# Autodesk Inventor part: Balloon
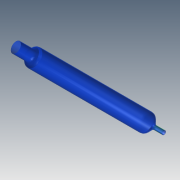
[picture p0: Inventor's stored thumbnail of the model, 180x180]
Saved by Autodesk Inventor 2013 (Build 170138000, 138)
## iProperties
Created: 2013-11
Part Number: Balloon
Material: Generic
Document SubType Name: Modeling
Designer: Warren
Density: 1 g/cm^3
Author: Warren
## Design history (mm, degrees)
sketch "Sketch1"
  geometry: L1 (-2.25, 0.05)-(-1.98, 0.05); L2 (-1.908, 0.08)-(-1.771, 0.22); L3 (-1.7, 0.25)-(1.7, 0.25); L4 (1.771, 0.22)-(1.908, 0.08); L5 (1.98, 0.05)-(2.25, 0.05); L6 (2.25, 0.06)-(1.98, 0.06); L7 (1.915, 0.087)-(1.779, 0.227); L8 (1.7, 0.26)-(-1.7, 0.26); L9 (-1.779, 0.227)-(-1.915, 0.087); L10 (-1.98, 0.06)-(-2.25, 0.06); L11 (2.25, 0.05)-(2.25, 0.06); L12 (-2.25, 0.06)-(-2.25, 0.05); L13 (0, 0)-(1.838, 0); L14 (0, 0)-(0, 0.582); A1 r 0.1 centre (-1.98, 0.15) between (-1.98, 0.05) and (-1.908, 0.08); A2 r 0.1 centre (-1.7, 0.15) between (-1.7, 0.25) and (-1.771, 0.22); A3 r 0.1 centre (1.7, 0.15) between (1.771, 0.22) and (1.7, 0.25); A4 r 0.1 centre (1.98, 0.15) between (1.908, 0.08) and (1.98, 0.05); A5 r 0.09 centre (1.98, 0.15) between (1.915, 0.087) and (1.98, 0.06); A6 r 0.11 centre (1.7, 0.15) between (1.779, 0.227) and (1.7, 0.26); A7 r 0.11 centre (-1.7, 0.15) between (-1.7, 0.26) and (-1.779, 0.227); A8 r 0.09 centre (-1.98, 0.15) between (-1.98, 0.06) and (-1.915, 0.087); 1 further point
  constraints: 28 end point, 16 point on circle, 8 centre point, 8 tangent, 4 perpendicular, 3 collinear, 3 equal radius, 2 equal length, 2 parallel, 1 horizontal alignment, 1 midpoint, 1 vertical alignment, 8 other
  dimensions: "d2" = 0.1 radius of A1; "d3" = 0.05 vertical distance of L1.start L13.start; "d4" = 0.01 distance between parallel lines of L5 L6; "d7" = 3.4 distance of A3.centre A2.centre; "d8" = 4.5 distance of L5.end L1.start
revolve "Revolution1" sketch "Sketch1" stored, may be unused: angle "d5" = 90 deg
thicken "Thicken1" dims "d11" = 0.1, "d12" = 0.1
thicken "Thicken2" dims "d13" = 0.1, "d14" = 0.1
body "Solid1"
